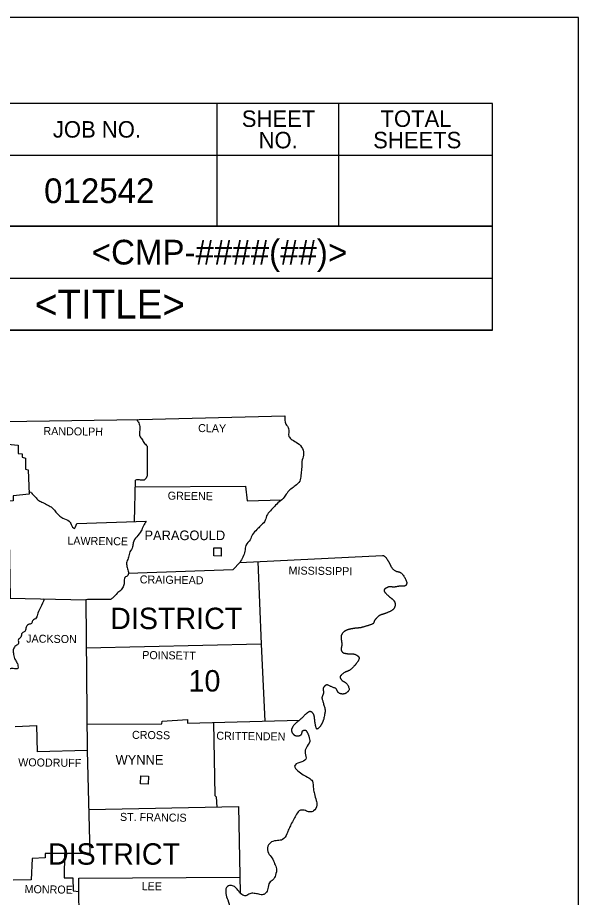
# Model space of a CAD drawing. Extents: x -819161 to 80911, y -6604 to 768454.
# Drawn here: x 80679.9 to 80911.3, y -4115 to -3751.8 of the extents above; entities that cross this region are included whole.
import ezdxf

# ---------------------------------------------------------------- set-up
doc = ezdxf.new("R2010")
doc.units = 0
for name, color, linetype in [('SHET_Annotations', 7, 'Continuous'), ('SHET_Border-Lines', 7, 'Continuous'), ('SHET_Border-Text', 7, 'Continuous')]:
    doc.layers.add(name, color=color, linetype=linetype)

msp = doc.modelspace()

# ---------------------------------------------------------------- linework, layer by layer
at = {"layer": 'SHET_Annotations'}
for p, q in [((80729.68, -3918.66), (80729.08, -3917.66)), ((80733.03, -3928.27), (80733.42, -3928.64)), ((80733.16, -3941.63), (80733.42, -3941.16)), ((80685.5, -3947.89), (80684.59, -3947.62)), ((80732.98, -3959.66), (80733.01, -3959.62)), ((80678.96, -4044.51), (80687.82, -4044.03))]:
    msp.add_line(p, q, dxfattribs=at)
for points in [[(80364.67, -3919.76), (80490.06, -3919.85), (80600.19, -3919.63), (80730.03, -3917.64), (80790.25, -3916.23)], [(80671.53, -3918.54), (80671.26, -3920.9), (80672.8, -3921.13), (80672.67, -3922.01), (80674.48, -3922.4), (80674.61, -3923.68), (80675.49, -3924.21), (80675.71, -3927.92), (80680.12, -3928.36), (80680.16, -3931.75), (80681.8, -3931.93), (80681.75, -3933.25), (80683.16, -3933.69), (80683.12, -3938.19), (80684.31, -3938.41), (80684.62, -3948.55), (80678.05, -3949.17), (80678.14, -3951.33), (80676.15, -3951.46), (80676.81, -3991.45), (80708.07, -3992.15), (80708.6, -4054.4), (80688.19, -4054.93), (80687.82, -4044.03)], [(80733.42, -3928.64), (80733.42, -3941.16)], [(80728.16, -3959.79), (80728.53, -3942.68)], [(80728.47, -3945.51), (80773.98, -3945.29), (80774.6, -3951.33), (80788.82, -3950.83)], [(80704.41, -3960.58), (80733.01, -3959.62)], [(80771.6, -3976.76), (80830.51, -3973.81)], [(80725.58, -3981.09), (80768.87, -3979.67), (80771.6, -3976.76)], [(80779.08, -3976.39), (80780.38, -4010.49), (80781.94, -4042.24)], [(80718.21, -3992.02), (80708.78, -3991.98), (80708.07, -3992.15)], [(80780.38, -4010.49), (80708.24, -4012.14)], [(80708.51, -4043.52), (80739.46, -4043.34), (80739.55, -4042.28), (80749.96, -4041.53), (80750, -4043.12), (80796.23, -4041.85)], [(80760.8, -4042.82), (80761.24, -4073.01), (80761.9, -4073.49), (80762.18, -4077.73)], [(80708.6, -4054.4), (80709.79, -4096.86), (80691.32, -4096.95), (80691.23, -4098.67), (80685.9, -4099.02), (80685.45, -4107.8), (80678.1, -4107.84)], [(80709.28, -4078.79), (80771.12, -4077.55)], [(80771.12, -4077.55), (80771.76, -4113.08)], [(80699.26, -4096.91), (80699.12, -4107), (80702.69, -4107), (80702.87, -4112.34), (80705.2, -4112.6)], [(80708.35, -4175.86), (80715.61, -4175.38), (80715.57, -4159.69), (80709.84, -4159.25), (80710.14, -4128.47), (80705.29, -4127.77), (80705.16, -4107.05), (80771.65, -4106.6)]]:
    msp.add_lwpolyline(points, dxfattribs=at)
for points in [[(80760.85, -3973.99), (80760.93, -3970.64), (80763.98, -3970.72), (80763.89, -3974.08)], [(80730.69, -4068.16), (80730.78, -4064.81), (80733.95, -4064.9), (80733.86, -4068.25)]]:
    msp.add_lwpolyline(points, close=True, dxfattribs=at)
for points in [[(80729.68, -3918.66), (80730.38, -3920.55), (80730.25, -3922.67), (80730.29, -3924.56), (80731.26, -3925.93), (80732.32, -3927.56), (80733.03, -3928.27)], [(80790.25, -3916.23), (80790.65, -3919.63), (80791.71, -3921.39), (80791.88, -3924.65), (80793.21, -3926.06), (80795.45, -3927.43), (80797.44, -3929.72), (80797.88, -3932.37), (80797.26, -3935.06), (80797.13, -3938.06), (80796.82, -3940.7), (80796.38, -3943.13), (80794.48, -3945.07), (80792.72, -3946.43), (80791.09, -3948.06), (80789.94, -3949.83), (80787.87, -3951.68), (80785.89, -3953.62), (80784.26, -3955.34), (80782.67, -3957.5), (80781.83, -3959.88), (80780.11, -3961.6), (80778.7, -3963.14), (80776.81, -3965.21), (80775.88, -3967.37), (80774.12, -3969.71), (80773.68, -3972.05), (80771.6, -3976.76)], [(80733.16, -3941.63), (80732.14, -3942.68), (80730.16, -3942.64), (80728.53, -3942.68)], [(80685.5, -3947.89), (80687.17, -3949.65), (80688.72, -3951.15), (80690.39, -3951.99), (80692.42, -3953.13), (80694.18, -3954.1), (80695.37, -3955.56), (80696.96, -3957.19), (80698.59, -3958.47), (80701.19, -3959.7), (80702.03, -3961.03), (80703.22, -3962.66), (80704.41, -3960.58)], [(80732.98, -3959.66), (80731.84, -3961.55), (80730.91, -3963.71), (80729.06, -3966.14), (80727.65, -3968.56), (80727.38, -3970.24), (80726.28, -3972.4), (80725.71, -3974.52), (80725, -3976.41), (80725, -3978.35), (80725.53, -3980.29), (80725.4, -3982.1), (80724.21, -3982.94), (80723.94, -3985.19), (80723.41, -3986.73), (80722.4, -3988.32), (80720.95, -3989.46), (80719.4, -3991.23), (80718.21, -3992.02)], [(80690.86, -3991.76), (80689.42, -3995.28), (80688.28, -3997.62), (80687.62, -3999.65), (80686.12, -4000.79), (80685.63, -4001.9), (80684.35, -4002.34), (80683.34, -4003.88), (80682.9, -4005.25), (80681.8, -4005.86), (80681.22, -4007.63), (80680.25, -4008.55), (80680.3, -4010.1), (80679.15, -4011.15), (80678.22, -4012.39), (80678.18, -4014.15), (80678.62, -4016.36), (80679.41, -4017.72), (80680.08, -4019.4), (80680.03, -4020.5), (80678.09, -4020.5), (80676.42, -4020.76)], [(80800.13, -4048.5), (80800.44, -4050.7), (80799.07, -4053.13), (80798.59, -4055.51), (80798.85, -4057.93), (80796.38, -4059.25), (80794.18, -4060.84), (80795.45, -4062.65), (80797.75, -4064.41), (80800.08, -4065.69), (80801.54, -4067.06), (80801.98, -4070.19), (80802.38, -4072.26), (80803.13, -4074.99), (80803.43, -4076.98), (80802.07, -4079.27), (80800.44, -4079.75), (80798.67, -4079.18), (80796.65, -4079.05), (80795.01, -4080.64), (80793.87, -4082.75), (80792.72, -4084.96), (80791.84, -4086.81), (80791, -4088.79), (80789.28, -4091.13), (80787.21, -4091.53), (80784.7, -4092.14), (80783.24, -4093.86), (80783.46, -4096.73), (80784.87, -4098.71), (80785.98, -4101.09), (80786.77, -4103.21), (80786.33, -4105.81), (80785.27, -4107.75), (80783.9, -4108.94), (80783.24, -4111.41), (80782.27, -4113.26), (80781.3, -4113.88), (80779.45, -4113.7), (80777.47, -4113.35), (80775.75, -4113.48), (80774.07, -4114.36), (80772.44, -4113.79), (80770.77, -4111.98), (80769.4, -4110.57), (80767.81, -4110.04), (80766.18, -4110.88), (80765.87, -4113.44), (80766.62, -4116.08), (80767.37, -4119.65), (80766.67, -4121.77), (80766.4, -4125.39)]]:
    msp.add_spline(points, degree=3, dxfattribs=at)
msp.add_open_spline([(80830.51, -3973.81), (80830.81, -3973.85), (80831.09, -3973.98), (80831.34, -3974.17), (80831.61, -3974.37), (80831.83, -3974.6), (80832.01, -3974.86), (80832.2, -3975.15), (80832.39, -3975.43), (80832.57, -3975.73), (80832.66, -3975.87), (80832.75, -3976.02), (80832.84, -3976.17), (80832.92, -3976.31), (80833.02, -3976.45), (80833.11, -3976.59), (80833.22, -3976.78), (80833.34, -3976.97), (80833.43, -3977.17), (80833.53, -3977.37), (80833.61, -3977.57), (80833.7, -3977.77), (80833.79, -3977.97), (80833.89, -3978.17), (80833.98, -3978.37), (80834.08, -3978.57), (80834.2, -3978.75), (80834.34, -3978.93), (80834.79, -3979.48), (80835.34, -3979.91), (80835.97, -3980.25), (80836.13, -3980.33), (80836.29, -3980.4), (80836.46, -3980.44), (80836.63, -3980.48), (80836.8, -3980.51), (80836.98, -3980.55), (80837.15, -3980.59), (80837.32, -3980.63), (80837.49, -3980.67), (80837.66, -3980.72), (80837.81, -3980.8), (80837.96, -3980.91), (80838.59, -3981.41), (80839.03, -3982), (80839.45, -3982.67), (80839.86, -3983.31), (80840.2, -3983.93), (80840.42, -3984.66), (80840.47, -3984.8), (80840.49, -3984.95), (80840.49, -3985.09), (80840.49, -3985.25), (80840.48, -3985.4), (80840.44, -3985.56), (80840.39, -3985.72), (80840.34, -3985.86), (80840.24, -3985.99), (80840.2, -3986.06), (80840.15, -3986.12), (80840.09, -3986.18), (80840.06, -3986.21), (80840.03, -3986.23), (80840, -3986.26), (80839.97, -3986.29), (80839.93, -3986.31), (80839.9, -3986.33), (80839.72, -3986.43), (80839.54, -3986.51), (80839.35, -3986.53), (80839.16, -3986.56), (80838.98, -3986.56), (80838.79, -3986.55), (80838.61, -3986.53), (80838.43, -3986.51), (80838.24, -3986.5), (80838.15, -3986.49), (80838.06, -3986.49), (80837.97, -3986.49), (80837.87, -3986.49), (80837.78, -3986.49), (80837.69, -3986.51), (80837.29, -3986.57), (80836.9, -3986.64), (80836.5, -3986.71), (80836.1, -3986.78), (80835.71, -3986.84), (80835.31, -3986.91), (80835.12, -3986.94), (80834.93, -3986.92), (80834.74, -3986.9), (80834.55, -3986.87), (80834.36, -3986.83), (80834.17, -3986.8), (80833.98, -3986.77), (80833.78, -3986.75), (80833.59, -3986.73), (80833.5, -3986.72), (80833.4, -3986.73), (80833.3, -3986.75), (80833.21, -3986.76), (80833.11, -3986.78), (80833.02, -3986.82), (80832.79, -3986.9), (80832.58, -3986.99), (80832.36, -3987.1), (80832.14, -3987.21), (80831.93, -3987.33), (80831.72, -3987.47), (80831.54, -3987.59), (80831.39, -3987.73), (80831.25, -3987.9), (80831.2, -3987.97), (80831.16, -3988.05), (80831.14, -3988.13), (80831.12, -3988.17), (80831.12, -3988.21), (80831.11, -3988.25), (80831.11, -3988.28), (80831.11, -3988.32), (80831.12, -3988.36), (80831.17, -3988.55), (80831.24, -3988.72), (80831.36, -3988.87), (80831.49, -3989.06), (80831.63, -3989.24), (80831.79, -3989.4), (80832.13, -3989.75), (80832.48, -3990.1), (80832.84, -3990.43), (80833.02, -3990.6), (80833.21, -3990.77), (80833.4, -3990.93), (80833.59, -3991.08), (80833.79, -3991.22), (80833.98, -3991.37), (80834.17, -3991.53), (80834.36, -3991.68), (80834.55, -3991.83), (80834.75, -3992), (80834.92, -3992.18), (80835.09, -3992.37), (80835.22, -3992.52), (80835.33, -3992.68), (80835.42, -3992.86), (80835.51, -3993.03), (80835.58, -3993.21), (80835.64, -3993.4), (80835.69, -3993.59), (80835.72, -3993.77), (80835.74, -3993.96), (80835.75, -3994.13), (80835.74, -3994.31), (80835.71, -3994.49), (80835.63, -3994.88), (80835.49, -3995.24), (80835.28, -3995.6), (80835.18, -3995.79), (80835.06, -3995.95), (80834.91, -3996.1), (80834.76, -3996.26), (80834.61, -3996.4), (80834.43, -3996.52), (80834.04, -3996.76), (80833.65, -3996.97), (80833.23, -3997.14), (80832.82, -3997.3), (80832.42, -3997.47), (80832, -3997.62), (80831.8, -3997.69), (80831.59, -3997.77), (80831.39, -3997.84), (80831.18, -3997.91), (80830.97, -3997.97), (80830.77, -3998.04), (80830.56, -3998.11), (80830.35, -3998.18), (80830.14, -3998.25), (80829.94, -3998.32), (80829.74, -3998.41), (80829.54, -3998.5), (80829.32, -3998.6), (80829.12, -3998.73), (80828.93, -3998.87), (80828.74, -3999.02), (80828.56, -3999.17), (80828.39, -3999.34), (80828.22, -3999.51), (80828.06, -3999.69), (80827.9, -3999.86), (80827.73, -4000.04), (80827.57, -4000.21), (80827.42, -4000.4), (80827.31, -4000.53), (80827.22, -4000.69), (80827.15, -4000.85), (80827.07, -4001.01), (80827.02, -4001.19), (80826.95, -4001.36), (80826.89, -4001.52), (80826.82, -4001.68), (80826.73, -4001.84), (80826.64, -4001.98), (80826.51, -4002.09), (80826.36, -4002.16), (80825.97, -4002.33), (80825.58, -4002.48), (80825.18, -4002.6), (80824.78, -4002.72), (80824.38, -4002.83), (80823.98, -4002.95), (80823.57, -4003.08), (80823.16, -4003.2), (80822.75, -4003.33), (80822.34, -4003.45), (80821.93, -4003.56), (80821.51, -4003.66), (80821.33, -4003.7), (80821.15, -4003.73), (80820.96, -4003.75), (80820.78, -4003.76), (80820.6, -4003.78), (80820.41, -4003.79), (80820.23, -4003.8), (80820.04, -4003.81), (80819.86, -4003.83), (80819.67, -4003.84), (80819.49, -4003.86), (80819.31, -4003.88), (80818.9, -4003.93), (80818.5, -4004), (80818.09, -4004.07), (80817.69, -4004.15), (80817.28, -4004.23), (80816.88, -4004.32), (80816.66, -4004.37), (80816.44, -4004.43), (80816.23, -4004.49), (80816.01, -4004.55), (80815.8, -4004.63), (80815.6, -4004.73), (80815.39, -4004.82), (80815.19, -4004.93), (80815, -4005.06), (80814.9, -4005.12), (80814.8, -4005.19), (80814.7, -4005.27), (80814.6, -4005.34), (80814.51, -4005.42), (80814.41, -4005.51), (80814.11, -4005.79), (80813.88, -4006.1), (80813.67, -4006.46), (80813.57, -4006.63), (80813.51, -4006.8), (80813.47, -4006.99), (80813.43, -4007.17), (80813.4, -4007.35), (80813.4, -4007.54), (80813.4, -4007.78), (80813.41, -4008.02), (80813.43, -4008.25), (80813.46, -4008.49), (80813.49, -4008.73), (80813.53, -4008.97), (80813.56, -4009.21), (80813.6, -4009.45), (80813.63, -4009.69), (80813.67, -4009.93), (80813.69, -4010.17), (80813.71, -4010.4), (80813.72, -4010.65), (80813.68, -4010.9), (80813.64, -4011.15), (80813.6, -4011.41), (80813.53, -4011.65), (80813.49, -4011.91), (80813.45, -4012.15), (80813.42, -4012.41), (80813.43, -4012.66), (80813.44, -4012.78), (80813.46, -4012.91), (80813.5, -4013.03), (80813.52, -4013.09), (80813.54, -4013.16), (80813.57, -4013.22), (80813.6, -4013.28), (80813.63, -4013.34), (80813.66, -4013.4), (80813.79, -4013.61), (80813.95, -4013.78), (80814.16, -4013.92), (80814.36, -4014.05), (80814.57, -4014.14), (80814.8, -4014.19), (80815.04, -4014.24), (80815.27, -4014.28), (80815.51, -4014.32), (80815.75, -4014.35), (80815.98, -4014.39), (80816.22, -4014.42), (80816.41, -4014.44), (80816.59, -4014.46), (80816.78, -4014.46), (80816.97, -4014.46), (80817.16, -4014.45), (80817.34, -4014.45), (80817.53, -4014.45), (80817.72, -4014.44), (80817.91, -4014.44), (80818.1, -4014.44), (80818.28, -4014.47), (80818.47, -4014.5), (80818.89, -4014.58), (80819.29, -4014.72), (80819.67, -4014.91), (80819.87, -4015), (80820.04, -4015.11), (80820.21, -4015.24), (80820.3, -4015.31), (80820.37, -4015.38), (80820.45, -4015.45), (80820.53, -4015.53), (80820.6, -4015.6), (80820.67, -4015.69), (80820.76, -4015.82), (80820.82, -4015.96), (80820.84, -4016.1), (80820.87, -4016.25), (80820.86, -4016.41), (80820.81, -4016.55), (80820.7, -4016.86), (80820.59, -4017.15), (80820.41, -4017.41), (80820.16, -4017.79), (80819.91, -4018.15), (80819.64, -4018.5), (80819.51, -4018.68), (80819.37, -4018.85), (80819.23, -4019.02), (80819.08, -4019.2), (80818.93, -4019.36), (80818.78, -4019.53), (80818.19, -4020.16), (80817.58, -4020.73), (80816.88, -4021.25), (80816.74, -4021.36), (80816.59, -4021.44), (80816.42, -4021.5), (80816.26, -4021.56), (80816.1, -4021.63), (80815.93, -4021.68), (80815.77, -4021.74), (80815.6, -4021.8), (80815.43, -4021.86), (80815.26, -4021.92), (80815.1, -4022), (80814.94, -4022.09), (80814.56, -4022.3), (80814.22, -4022.55), (80813.88, -4022.83), (80813.72, -4022.96), (80813.58, -4023.11), (80813.44, -4023.26), (80813.3, -4023.4), (80813.18, -4023.55), (80813.09, -4023.72), (80812.96, -4023.96), (80813.01, -4024.29), (80813.14, -4024.54), (80813.29, -4024.84), (80813.46, -4025.12), (80813.71, -4025.35), (80813.84, -4025.47), (80813.96, -4025.58), (80814.11, -4025.66), (80814.26, -4025.74), (80814.4, -4025.82), (80814.55, -4025.9), (80814.7, -4025.98), (80814.84, -4026.06), (80814.99, -4026.14), (80815.14, -4026.22), (80815.26, -4026.33), (80815.38, -4026.45), (80815.91, -4026.96), (80816.27, -4027.58), (80816.53, -4028.22), (80816.73, -4028.71), (80816.72, -4029.4), (80816.4, -4029.85), (80816.34, -4029.93), (80816.27, -4030.01), (80816.2, -4030.08), (80816.13, -4030.15), (80816.06, -4030.22), (80815.98, -4030.28), (80815.84, -4030.41), (80815.69, -4030.51), (80815.53, -4030.61), (80815.22, -4030.8), (80814.89, -4030.91), (80814.55, -4030.99), (80814.2, -4031.07), (80813.84, -4031.06), (80813.49, -4031), (80813.13, -4030.94), (80812.79, -4030.83), (80812.47, -4030.6), (80812.29, -4030.47), (80812.15, -4030.33), (80812.05, -4030.14), (80811.95, -4029.95), (80811.86, -4029.76), (80811.76, -4029.57), (80811.66, -4029.39), (80811.57, -4029.21), (80811.46, -4029.03), (80811.36, -4028.86), (80811.2, -4028.73), (80811.02, -4028.66), (80810.46, -4028.41), (80809.9, -4028.23), (80809.34, -4028), (80808.84, -4027.79), (80808.35, -4027.54), (80807.84, -4027.33), (80807.7, -4027.28), (80807.54, -4027.27), (80807.39, -4027.31), (80807.24, -4027.35), (80807.09, -4027.41), (80806.95, -4027.52), (80806.8, -4027.63), (80806.66, -4027.75), (80806.54, -4027.89), (80806.47, -4027.96), (80806.41, -4028.03), (80806.35, -4028.11), (80806.28, -4028.19), (80806.22, -4028.26), (80806.17, -4028.35), (80806.06, -4028.52), (80805.98, -4028.7), (80805.97, -4028.9), (80805.96, -4029.08), (80805.98, -4029.27), (80806.02, -4029.45), (80806.06, -4029.64), (80806.11, -4029.82), (80806.14, -4030.01), (80806.16, -4030.1), (80806.17, -4030.19), (80806.18, -4030.28), (80806.19, -4030.37), (80806.19, -4030.46), (80806.17, -4030.55), (80806.13, -4030.76), (80806.07, -4030.96), (80805.99, -4031.16), (80805.91, -4031.37), (80805.82, -4031.56), (80805.74, -4031.77), (80805.66, -4031.97), (80805.59, -4032.17), (80805.54, -4032.37), (80805.5, -4032.57), (80805.5, -4032.78), (80805.55, -4032.98), (80805.72, -4033.58), (80805.91, -4034.18), (80806.08, -4034.78), (80806.31, -4035.59), (80806.54, -4036.4), (80806.74, -4037.21), (80806.89, -4037.81), (80806.8, -4038.45), (80806.7, -4039.06), (80806.54, -4039.97), (80806.36, -4040.87), (80806.08, -4041.75), (80806, -4041.99), (80805.92, -4042.23), (80805.83, -4042.47), (80805.73, -4042.7), (80805.63, -4042.93), (80805.51, -4043.15), (80805.4, -4043.38), (80805.28, -4043.6), (80805.15, -4043.82), (80805.03, -4044.05), (80804.9, -4044.27), (80804.76, -4044.48), (80804.55, -4044.81), (80804.27, -4045.05), (80803.93, -4045.3), (80803.79, -4045.41), (80803.64, -4045.46), (80803.49, -4045.49), (80803.43, -4045.51), (80803.37, -4045.5), (80803.32, -4045.46), (80803.26, -4045.43), (80803.23, -4045.38), (80803.21, -4045.32), (80803.07, -4044.84), (80802.94, -4044.36), (80802.85, -4043.87), (80802.76, -4043.37), (80802.66, -4042.87), (80802.6, -4042.37), (80802.55, -4041.97), (80802.5, -4041.57), (80802.45, -4041.18), (80802.43, -4040.98), (80802.41, -4040.78), (80802.38, -4040.58), (80802.36, -4040.38), (80802.32, -4040.19), (80802.29, -4039.99), (80802.26, -4039.85), (80802.22, -4039.72), (80802.17, -4039.59), (80802.11, -4039.46), (80802.04, -4039.34), (80801.96, -4039.22), (80801.88, -4039.1), (80801.79, -4038.99), (80801.69, -4038.89), (80801.59, -4038.77), (80801.49, -4038.67), (80801.36, -4038.58), (80801.16, -4038.43), (80800.94, -4038.34), (80800.72, -4038.31), (80800.51, -4038.29), (80800.27, -4038.33), (80800.08, -4038.44), (80799.94, -4038.53), (80799.81, -4038.63), (80799.67, -4038.72), (80799.54, -4038.82), (80799.4, -4038.92), (80799.27, -4039.02), (80799, -4039.23), (80798.74, -4039.44), (80798.5, -4039.68), (80798.19, -4039.97), (80797.89, -4040.27), (80797.59, -4040.56), (80797.29, -4040.86), (80796.99, -4041.15), (80796.69, -4041.44), (80796.51, -4041.61), (80796.33, -4041.77), (80796.14, -4041.92), (80795.95, -4042.08), (80795.76, -4042.23), (80795.57, -4042.38), (80795.38, -4042.54), (80795.19, -4042.69), (80795, -4042.85), (80794.81, -4043), (80794.62, -4043.17), (80794.44, -4043.34), (80794.14, -4043.62), (80793.88, -4043.94), (80793.64, -4044.28), (80793.52, -4044.45), (80793.43, -4044.62), (80793.33, -4044.8), (80793.23, -4044.97), (80793.15, -4045.14), (80793.07, -4045.32), (80793, -4045.51), (80792.96, -4045.71), (80792.95, -4045.9), (80792.94, -4046.11), (80792.97, -4046.33), (80793.03, -4046.53), (80793.11, -4046.76), (80793.2, -4046.97), (80793.33, -4047.16), (80793.4, -4047.27), (80793.47, -4047.37), (80793.55, -4047.46), (80793.59, -4047.51), (80793.64, -4047.56), (80793.68, -4047.61), (80793.73, -4047.66), (80793.77, -4047.7), (80793.82, -4047.75), (80793.96, -4047.87), (80794.1, -4047.97), (80794.25, -4048.06), (80794.39, -4048.15), (80794.53, -4048.21), (80794.68, -4048.25), (80794.83, -4048.3), (80794.97, -4048.33), (80795.11, -4048.34), (80795.26, -4048.36), (80795.4, -4048.37), (80795.54, -4048.36), (80795.65, -4048.36), (80795.76, -4048.35), (80795.87, -4048.33), (80795.99, -4048.3), (80796.1, -4048.27), (80796.2, -4048.23), (80796.32, -4048.18), (80796.43, -4048.13), (80796.54, -4048.08), (80796.65, -4048.02), (80796.76, -4047.96), (80796.87, -4047.88), (80796.99, -4047.79), (80797.09, -4047.68), (80797.14, -4047.53), (80797.19, -4047.39), (80797.22, -4047.24), (80797.25, -4047.09), (80797.28, -4046.95), (80797.3, -4046.8), (80797.33, -4046.65), (80797.36, -4046.52), (80797.43, -4046.4), (80797.53, -4046.29), (80797.61, -4046.2), (80797.71, -4046.14), (80797.82, -4046.09), (80797.95, -4046.03), (80798.07, -4045.98), (80798.2, -4045.95), (80798.31, -4045.91), (80798.44, -4045.9), (80798.56, -4045.92), (80798.67, -4045.94), (80798.77, -4045.99), (80798.85, -4046.07), (80798.93, -4046.16), (80799, -4046.24), (80799.06, -4046.34), (80799.13, -4046.43), (80799.2, -4046.52), (80799.26, -4046.62), (80799.39, -4046.81), (80799.49, -4047), (80799.6, -4047.21), (80799.82, -4047.62), (80799.97, -4048.06), (80800.13, -4048.5)], degree=3, dxfattribs=at)
at = {"layer": 'SHET_Border-Lines'}
for p, q in [((80762.19, -3787.17), (80762.19, -3837.86)), ((80812.33, -3787.17), (80812.33, -3837.86)), ((80875.91, -3808.65), (80564.52, -3808.65)), ((80875.91, -3808.5), (80875.91, -3808.5)), ((80875.91, -3837.86), (80564.52, -3837.86)), ((80585.9, -3837.86), (80875.91, -3837.86)), ((80564.52, -3859.34), (80875.91, -3859.34)), ((80875.91, -3880.81), (80564.52, -3880.81))]:
    msp.add_line(p, q, dxfattribs=at)
for points in [[(78502.99, -5310.09), (80911.32, -5310.09), (80911.32, -3751.75), (78502.99, -3751.75)], [(80282.17, -3859.34), (80564.52, -3859.34), (80564.52, -3880.81), (80875.91, -3880.81), (80875.91, -3787.17), (80282.17, -3787.17)]]:
    msp.add_lwpolyline(points, close=True, dxfattribs=at)

# ---------------------------------------------------------------- texts
at = {"layer": 'SHET_Annotations'}
for s, height, p in [('012542', 10.2, (80690.85, -3828.36)), ('<CMP-####(##)>', 10.2, (80710.53, -3853.7)), ('<TITLE>', 11.9, (80687.05, -3876.03)), ('PARAGOULD', 3.968, (80732.26, -3967.51)), ('DISTRICT', 8.845, (80718.12, -4004.25)), ('10', 8.845, (80750.45, -4030.01)), ('WYNNE', 3.968, (80720.34, -4060.18)), ('DISTRICT', 8.845, (80692.42, -4101.52))]:
    msp.add_text(s, height=height, dxfattribs=at).set_placement(p)
for s, height, rotation, p in [('CLAY', 3.307, 359.3364, (80754.39, -3922.88)), ('RANDOLPH', 3.307, 359.2573, (80690.57, -3924.08)), ('GREENE', 3.307, 359.2711, (80741.83, -3950.79)), ('LAWRENCE', 3.307, 359.2655, (80700.43, -3969.36)), ('MISSISSIPPI', 3.3066, 359.2098, (80791.71, -3981.66)), ('CRAIGHEAD', 3.307, 359.1888, (80730.32, -3985.36)), ('JACKSON', 3.307, 359.2575, (80683.44, -4009.78)), ('POINSETT', 3.307, 359.1979, (80731.33, -4016.57)), ('CROSS', 3.307, 359.3097, (80727.12, -4049.55)), ('CRITTENDEN', 3.307, 359.2782, (80761.9, -4049.9)), ('WOODRUFF', 3.307, 359.2708, (80680.14, -4060.84)), ('ST. FRANCIS', 3.3066, 359.1956, (80722.14, -4083.41)), ('MONROE', 3.307, 359.1697, (80682.79, -4113.22)), ('LEE', 3.307, 359.3634, (80731.09, -4112.02))]:
    msp.add_text(s, height=height, rotation=rotation, dxfattribs=at).set_placement(p)
at = {"layer": 'SHET_Border-Text'}
for s, p in [('SHEET', (80772.42, -3796.89)), ('TOTAL', (80829.67, -3796.89)), ('JOB NO.', (80694.47, -3801.31)), ('NO.', (80779.35, -3805.73)), ('SHEETS', (80826.63, -3805.73))]:
    msp.add_text(s, height=6.8, dxfattribs=at).set_placement(p)

doc.saveas('drawing.dxf')
